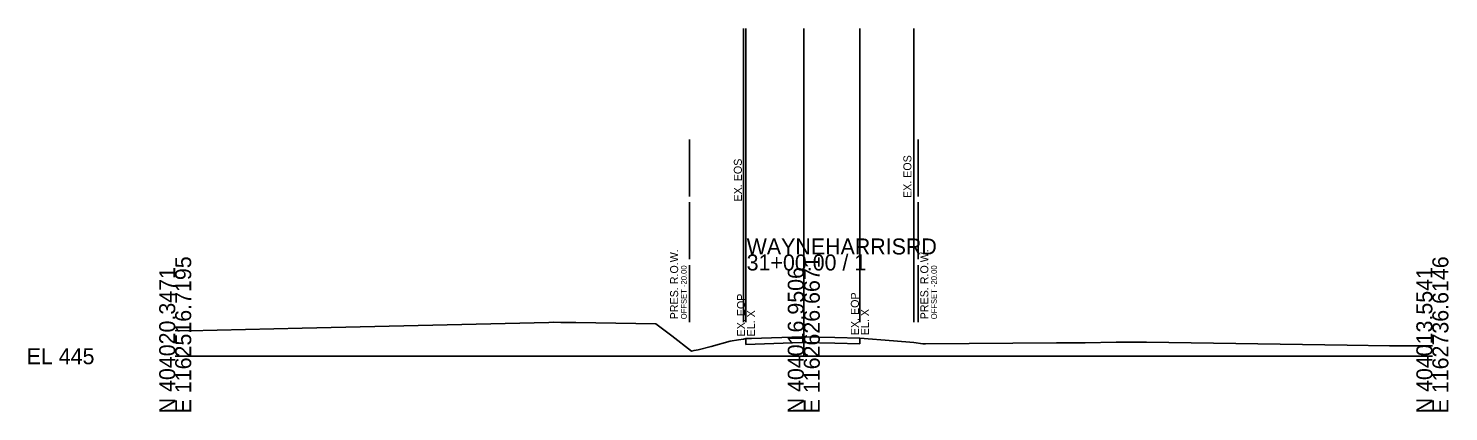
# Model space of a CAD drawing. Extents: x -26 to 223, y -10 to 1557.
# Drawn here: x -25.7 to 222.8, y 1490.3 to 1557.4 of the extents above; entities that cross this region are included whole.
import ezdxf

# ---------------------------------------------------------------- set-up
doc = ezdxf.new("R2010")
doc.units = 0
for name, color, linetype in [('DESIGN - SCRATCH - User 2', 7, 'Continuous'), ('DESIGN - SHEET - Light Grid', 7, 'Continuous'), ('DESIGN - TYPICAL - Finished Grade and Subgrade', 7, 'Continuous'), ('SURVEY - GROUND - Top of Ground', 7, 'Continuous'), ('SURVEY - PROPERTY - ROW Lines', 7, 'Continuous'), ('SURVEY - PROPERTY - ROW Lines Text', 7, 'Continuous')]:
    doc.layers.add(name, color=color, linetype=linetype)

msp = doc.modelspace()

# ---------------------------------------------------------------- linework, layer by layer
at = {"layer": 'DESIGN - SCRATCH - User 2'}
for p, q in [((99.46, 1505.96), (99.46, 1557.38)), ((99.88, 1505.96), (99.88, 1557.38)), ((110, 1505.96), (110, 1557.38)), ((119.83, 1505.96), (119.83, 1557.38)), ((129.24, 1505.96), (129.24, 1557.38))]:
    msp.add_line(p, q, dxfattribs=at)
at = {"layer": 'DESIGN - SHEET - Light Grid'}
for p, q in [((110, 1500), (110, 1517.81)), ((0, 1500), (110, 1500)), ((110, 1500), (220, 1500))]:
    msp.add_line(p, q, dxfattribs=at)
at = {"layer": 'DESIGN - TYPICAL - Finished Grade and Subgrade'}
for p, q in [((99.88, 1503.08), (99.88, 1502.08)), ((119.83, 1503.16), (119.83, 1502.16))]:
    msp.add_line(p, q, dxfattribs=at)
msp.add_lwpolyline([(99.88, 1502.08), (109.65, 1502.41), (109.98, 1502.4), (115.41, 1502.27), (119.83, 1502.16)], dxfattribs=at)
at = {"layer": 'SURVEY - GROUND - Top of Ground'}
msp.add_lwpolyline([(0, 1504.51), (2.39, 1504.47), (22.24, 1504.92), (65.36, 1505.92), (66.25, 1505.94), (67.47, 1505.91), (68.08, 1505.91), (70.11, 1505.88), (84.11, 1505.69), (86.93, 1503.56), (90.37, 1500.91), (90.81, 1501.01), (91.54, 1501.14), (93.8, 1501.73), (97.12, 1502.64), (98.56, 1502.85), (99.46, 1502.98), (99.88, 1503.08), (100.86, 1503.11), (109.64, 1503.41), (110, 1503.4), (115.43, 1503.27), (119.83, 1503.16), (125.67, 1502.68), (129.24, 1502.38), (130.85, 1502.18), (131.31, 1502.19), (154.24, 1502.35), (157.41, 1502.35), (159.23, 1502.34), (164.69, 1502.48), (169.97, 1502.45), (205.07, 1501.94), (212.47, 1501.84), (220, 1501.79)], dxfattribs=at)
at = {"layer": 'SURVEY - PROPERTY - ROW Lines'}
for p, q in [((90, 1527.96), (90, 1537.96)), ((130, 1527.96), (130, 1537.96)), ((90, 1516.96), (90, 1526.96)), ((130, 1516.96), (130, 1526.96)), ((90, 1505.96), (90, 1515.96)), ((130, 1505.96), (130, 1515.96))]:
    msp.add_line(p, q, dxfattribs=at)

# ---------------------------------------------------------------- texts
at = {"layer": 'DESIGN - SCRATCH - User 2'}
for s, p in [('EX. EOS', (99.16, 1527.09)), ('EX. EOS', (128.83, 1527.69)), ('EX. EOP', (99.72, 1503.47)), ('EX. EOP', (119.64, 1503.68)), ('EL. X', (101.47, 1503.47)), ('EL. X', (121.39, 1503.68))]:
    msp.add_text(s, height=1.4, rotation=90, dxfattribs=at).set_placement(p)
at = {"layer": 'DESIGN - SHEET - Light Grid'}
for s, p in [('WAYNEHARRISRD', (100, 1517.81)), ('31+00.00 / 1', (100, 1515.01)), ('EL 445', (-26, 1498.6))]:
    msp.add_text(s, height=2.8, dxfattribs=at).set_placement(p)
for s, p in [('E 1162516.7195', (2.8, 1490)), ('E 1162626.6671', (112.8, 1490)), ('E 1162736.6146', (222.8, 1490)), ('N 404020.3471', (0, 1490)), ('N 404016.9506', (110, 1490)), ('N 404013.5541', (220, 1490))]:
    msp.add_text(s, height=2.8, rotation=90, dxfattribs=at).set_placement(p)
at = {"layer": 'SURVEY - PROPERTY - ROW Lines Text'}
for s, height, p in [('PRES. R.O.W.', 1.4, (88.01, 1506.46)), ('PRES. R.O.W.', 1.4, (131.79, 1506.46)), ('OFFSET -20.00', 1, (89.51, 1506.46)), ('OFFSET -20.00', 1, (133.29, 1506.46))]:
    msp.add_text(s, height=height, rotation=90, dxfattribs=at).set_placement(p)

doc.saveas('drawing.dxf')
